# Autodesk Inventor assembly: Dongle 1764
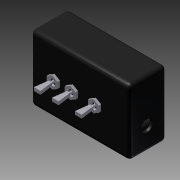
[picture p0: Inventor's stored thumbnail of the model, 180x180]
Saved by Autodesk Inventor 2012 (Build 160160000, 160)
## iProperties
Created: 2010-01
Part Number: Dongle 1764
Document SubType Name: Weldment
Designer: jgehrig
Weld Material: Welded Aluminum-6061
Author: jgehrig
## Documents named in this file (7)
- R:\CAD Archives\Electronics_1764\Dongle_1764\Dongle_1764\Dongle_1764.iam
- R:\CAD Archives\Electronics_1764\Dongle_1764\Dongle_1764\Dongle_Base_1764.ipt
- R:\CAD Archives\Electronics_1764\Dongle_1764\Dongle_1764\Dongle_Top_1764.ipt
- R:\CAD Archives\Electronics_1764\Dongle_1764\Dongle_1764\Dongle_Switch_1764.ipt
- R:\CAD Archives\Electronics_1764\Dongle_1764\Dongle_1764\Dongle_Hexagon_1764.ipt
- R:\CAD Archives\Electronics_1764\Dongle_1764\Dongle_1764\Dongle_Flat_1764.ipt
- R:\CAD Archives\Electronics_1764\Dongle_1764\Dongle_1764\Dongle_Blue_Box_1764.ipt
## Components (20 placed, 6 different names)
1. Dongle_Base_1764:1 — Mate:1, Mate:2, Angle:1, Mate:3, Mate:4, Mate:5, Mate:6, Mate:7, Mate:8, Angle:4, Mate:9, Mate:10, Mate:11, Mate:12, Mate:33, Mate:34, Mate:35
2. Dongle_Blue_Box_1764:1 — Mate:23, Flush:11, Flush:12, Flush:15, Mate:24, Flush:16, Mate:25, Mate:26
3. Dongle_Blue_Box_1764:2 — Mate:18, Flush:6, Flush:7, Mate:19, Flush:8, Flush:9, Mate:20, Mate:22
4. Dongle_Blue_Box_1764:3 — Mate:13, Flush:1, Flush:2, Mate:14, Flush:3, Flush:4, Mate:17, Mate:21
5. Dongle_Flat_1764:1 — Flush:15, Mate:24, Flush:16
6. Dongle_Flat_1764:2 — Mate:23, Flush:11, Flush:12, Flush:17
7. Dongle_Flat_1764:3 — Mate:19, Flush:8, Flush:9, Flush:10
8. Dongle_Flat_1764:4 — Mate:18, Flush:6, Flush:7
9. Dongle_Flat_1764:5 — Mate:14, Flush:3, Flush:4, Flush:5
10. Dongle_Flat_1764:6 — Mate:13, Flush:1, Flush:2
11. Dongle_Hexagon_1764:1 — Mate:1, Mate:2, Angle:1, Angle:2, Mate:31, Mate:32, Angle:9
12. Dongle_Hexagon_1764:2 — Mate:9, Mate:10, Angle:5, Mate:17, Flush:5, Mate:21
13. Dongle_Hexagon_1764:3 — Mate:7, Mate:8, Angle:4, Angle:5, Angle:6, Mate:20, Flush:10, Mate:22
14. Dongle_Hexagon_1764:4 — Mate:5, Mate:6, Angle:3, Mate:27, Mate:28, Angle:7
15. Dongle_Hexagon_1764:5 — Mate:3, Mate:4, Angle:2, Angle:3, Mate:29, Mate:30, Angle:8
16. Dongle_Hexagon_1764:6 — Mate:11, Mate:12, Angle:6, Mate:25, Flush:17, Mate:26
17. Dongle_Switch_1764:1 — Mate:31, Mate:32, Angle:9
18. Dongle_Switch_1764:1 — Mate:27, Mate:28, Angle:7
19. Dongle_Switch_1764:1 — Mate:29, Mate:30, Angle:8
20. Dongle_Top_1764:1 — Mate:33, Mate:34, Mate:35
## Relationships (57: Mate 33, Flush 15, Angle 9)
- Mate:1: Dongle_Base_1764:1 ↔ Dongle_Hexagon_1764:1
- Mate:2: Dongle_Base_1764:1 ↔ Dongle_Hexagon_1764:1
- Angle:1: Dongle_Base_1764:1 ↔ Dongle_Hexagon_1764:1
- Mate:3: Dongle_Base_1764:1 ↔ Dongle_Hexagon_1764:5
- Mate:4: Dongle_Base_1764:1 ↔ Dongle_Hexagon_1764:5
- Angle:2: Dongle_Hexagon_1764:1 ↔ Dongle_Hexagon_1764:5
- Mate:5: Dongle_Base_1764:1 ↔ Dongle_Hexagon_1764:4
- Mate:6: Dongle_Base_1764:1 ↔ Dongle_Hexagon_1764:4
- Angle:3: Dongle_Hexagon_1764:4 ↔ Dongle_Hexagon_1764:5
- Mate:7: Dongle_Base_1764:1 ↔ Dongle_Hexagon_1764:3
- Mate:8: Dongle_Base_1764:1 ↔ Dongle_Hexagon_1764:3
- Angle:4: Dongle_Base_1764:1 ↔ Dongle_Hexagon_1764:3
- Mate:9: Dongle_Base_1764:1 ↔ Dongle_Hexagon_1764:2
- Mate:10: Dongle_Base_1764:1 ↔ Dongle_Hexagon_1764:2
- Angle:5: Dongle_Hexagon_1764:2 ↔ Dongle_Hexagon_1764:3
- Mate:11: Dongle_Base_1764:1 ↔ Dongle_Hexagon_1764:6
- Mate:12: Dongle_Base_1764:1 ↔ Dongle_Hexagon_1764:6
- Angle:6: Dongle_Hexagon_1764:3 ↔ Dongle_Hexagon_1764:6
- Mate:13: Dongle_Blue_Box_1764:3 ↔ Dongle_Flat_1764:6
- Flush:1: Dongle_Blue_Box_1764:3 ↔ Dongle_Flat_1764:6
- Flush:2: Dongle_Blue_Box_1764:3 ↔ Dongle_Flat_1764:6
- Mate:14: Dongle_Blue_Box_1764:3 ↔ Dongle_Flat_1764:5
- Flush:3: Dongle_Blue_Box_1764:3 ↔ Dongle_Flat_1764:5
- Flush:4: Dongle_Blue_Box_1764:3 ↔ Dongle_Flat_1764:5
- Mate:17: Dongle_Blue_Box_1764:3 ↔ Dongle_Hexagon_1764:2
- Flush:5: Dongle_Flat_1764:5 ↔ Dongle_Hexagon_1764:2
- Mate:18: Dongle_Blue_Box_1764:2 ↔ Dongle_Flat_1764:4
- Flush:6: Dongle_Blue_Box_1764:2 ↔ Dongle_Flat_1764:4
- Flush:7: Dongle_Blue_Box_1764:2 ↔ Dongle_Flat_1764:4
- Mate:19: Dongle_Blue_Box_1764:2 ↔ Dongle_Flat_1764:3
- Flush:8: Dongle_Blue_Box_1764:2 ↔ Dongle_Flat_1764:3
- Flush:9: Dongle_Blue_Box_1764:2 ↔ Dongle_Flat_1764:3
- Mate:20: Dongle_Blue_Box_1764:2 ↔ Dongle_Hexagon_1764:3
- Flush:10: Dongle_Flat_1764:3 ↔ Dongle_Hexagon_1764:3
- Mate:21: Dongle_Blue_Box_1764:3 ↔ Dongle_Hexagon_1764:2
- Mate:22: Dongle_Blue_Box_1764:2 ↔ Dongle_Hexagon_1764:3
- Mate:23: Dongle_Blue_Box_1764:1 ↔ Dongle_Flat_1764:2
- Flush:11: Dongle_Blue_Box_1764:1 ↔ Dongle_Flat_1764:2
- Flush:12: Dongle_Blue_Box_1764:1 ↔ Dongle_Flat_1764:2
- Flush:15: Dongle_Blue_Box_1764:1 ↔ Dongle_Flat_1764:1
- Mate:24: Dongle_Blue_Box_1764:1 ↔ Dongle_Flat_1764:1
- Flush:16: Dongle_Blue_Box_1764:1 ↔ Dongle_Flat_1764:1
- Mate:25: Dongle_Blue_Box_1764:1 ↔ Dongle_Hexagon_1764:6
- Flush:17: Dongle_Flat_1764:2 ↔ Dongle_Hexagon_1764:6
- Mate:26: Dongle_Blue_Box_1764:1 ↔ Dongle_Hexagon_1764:6
- Mate:27: Dongle_Hexagon_1764:4 ↔ Dongle_Switch_1764:1
- Mate:28: Dongle_Hexagon_1764:4 ↔ Dongle_Switch_1764:1
- Angle:7: Dongle_Hexagon_1764:4 ↔ Dongle_Switch_1764:1
- Mate:29: Dongle_Hexagon_1764:5 ↔ Dongle_Switch_1764:1
- Mate:30: Dongle_Hexagon_1764:5 ↔ Dongle_Switch_1764:1
- Angle:8: Dongle_Hexagon_1764:5 ↔ Dongle_Switch_1764:1
- Mate:31: Dongle_Hexagon_1764:1 ↔ Dongle_Switch_1764:1
- Mate:32: Dongle_Hexagon_1764:1 ↔ Dongle_Switch_1764:1
- Angle:9: Dongle_Hexagon_1764:1 ↔ Dongle_Switch_1764:1
- Mate:33: Dongle_Base_1764:1 ↔ Dongle_Top_1764:1
- Mate:34: Dongle_Base_1764:1 ↔ Dongle_Top_1764:1
- Mate:35: Dongle_Base_1764:1 ↔ Dongle_Top_1764:1
